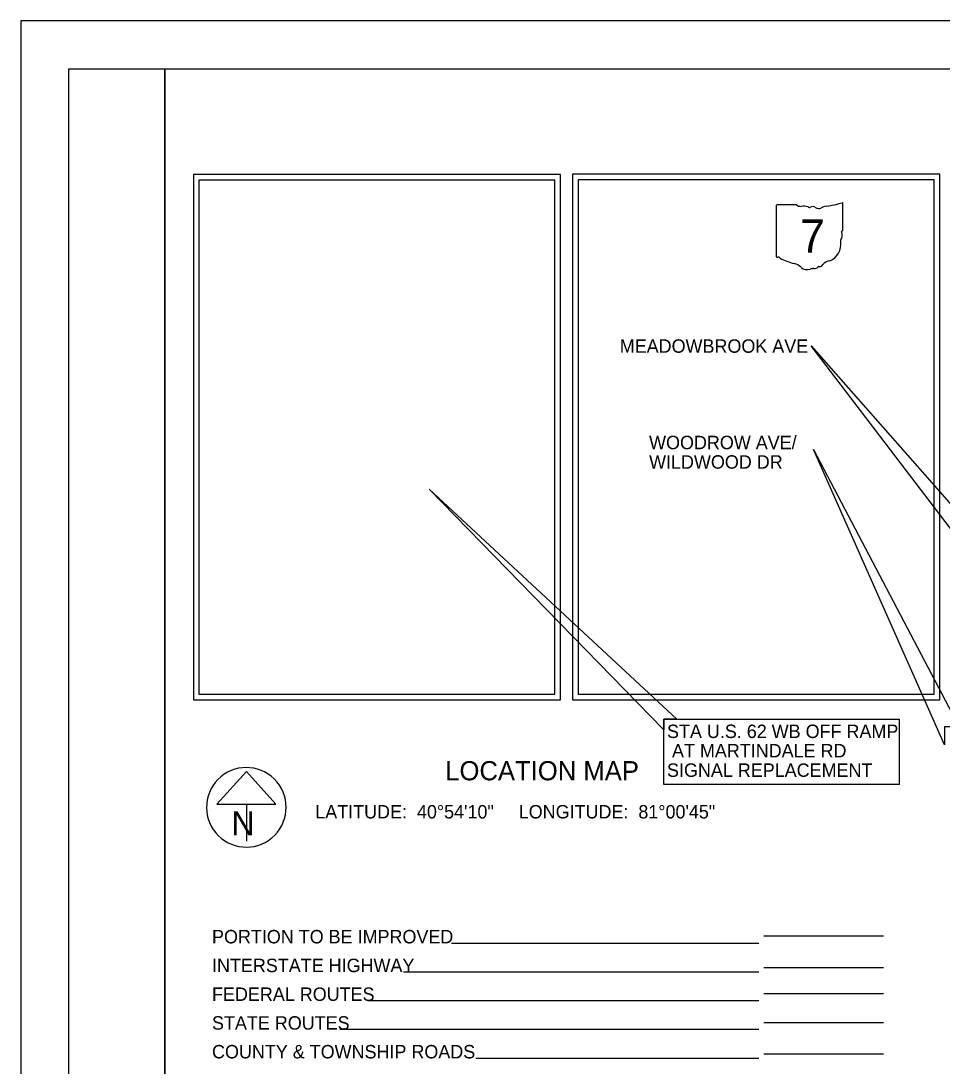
# Model space of a CAD drawing. Extents: x 0 to 29006, y 0 to 889393.
# Drawn here: x 0 to 9.61, y 11.1 to 22 of the extents above; entities that cross this region are included whole.
import ezdxf

# ---------------------------------------------------------------- set-up
doc = ezdxf.new("R2010")
doc.units = 0
for name, color, linetype in [('Default', 7, 'Continuous'), ('GM_X_State_Shield', 7, 'Continuous'), ('SH_Border', 7, 'Continuous'), ('SH_Cut_Line', 7, 'Continuous'), ('SH_Data', 7, 'Continuous'), ('SH_Text', 7, 'Continuous')]:
    doc.layers.add(name, color=color, linetype=linetype)

msp = doc.modelspace()

# ---------------------------------------------------------------- linework, layer by layer
at = {"layer": 'Default'}
for p, q in [((5.63, 20.399), (1.799, 20.399)), ((1.799, 20.399), (1.799, 14.916)), ((5.63, 14.916), (5.63, 20.399)), ((9.587, 20.401), (5.754, 20.401)), ((5.754, 20.401), (5.754, 14.916)), ((9.587, 14.916), (9.587, 20.401)), ((5.571, 20.34), (1.858, 20.34)), ((1.858, 20.34), (1.858, 14.975)), ((5.571, 14.975), (5.571, 20.34)), ((9.528, 20.342), (5.813, 20.342)), ((5.813, 20.342), (5.813, 14.975)), ((9.528, 14.975), (9.528, 20.342)), ((1.858, 14.975), (5.571, 14.975)), ((5.813, 14.975), (9.528, 14.975)), ((1.799, 14.916), (5.63, 14.916)), ((5.754, 14.916), (9.587, 14.916))]:
    msp.add_line(p, q, dxfattribs=at)
for points in [[(10.002, 16.307), (8.244, 18.612), (10.126, 16.474), (10.002, 16.474)], [(9.635, 14.448), (8.269, 17.529), (9.789, 14.637), (9.635, 14.637)], [(6.707, 14.603), (4.261, 17.114), (6.844, 14.715), (6.707, 14.715)], [(6.707, 14.715), (9.164, 14.715), (9.164, 14.036), (6.707, 14.036)]]:
    msp.add_lwpolyline(points, close=True, dxfattribs=at)
at = {"layer": 'GM_X_State_Shield'}
for p, q in [((7.88, 20.073), (7.88, 19.544)), ((8.091, 20.082), (7.887, 20.082)), ((8.576, 19.819), (8.576, 20.095)), ((8.576, 19.819), (8.576, 19.819))]:
    msp.add_line(p, q, dxfattribs=at)
for centre, radius, start, end in [((7.888, 20.074), 0.00806, 98.1301, 188.1301), ((8.139, 20.143), 0.0782, 231.6195, 271.1119), ((8.165, 19.785), 0.281, 80.4867, 94.9883), ((8.229, 20.077), 0.0226, 219.7921, 297.1024), ((8.262, 20.016), 0.0469, 54.4667, 119.1411), ((8.422, 19.92), 0.149, 97.3462, 120.7689), ((8.328, 20.802), 0.738, 275.8445, 288.9065), ((8.568, 20.096), 0.00775, 351.8621, 97.738), ((8.323, 20.099), 0.0564, 233.8562, 294.8282), ((8.604, 19.703), 0.0524, 136.8065, 186.9296), ((8.574, 19.798), 0.012, 107.944, 210.337), ((8.498, 19.763), 0.072, 340.033, 23.6496), ((8.568, 19.818), 0.00829, 289.6038, 7.7341), ((8.37, 19.668), 0.185, 292.3089, 8.9858), ((7.888, 19.543), 0.00814, 171.9584, 258.3066), ((7.889, 19.597), 0.0621, 267.339, 280.6039), ((7.902, 19.514), 0.0224, 29.7484, 93.2717), ((8.185, 19.989), 0.533, 240.4129, 257.1985), ((8.026, 19.307), 0.167, 47.1842, 75.836), ((8.206, 19.511), 0.106, 230.7004, 286.2918), ((8.267, 19.329), 0.087, 85.6951, 111.2099), ((8.275, 19.472), 0.0564, 268.777, 315.5493), ((8.326, 19.421), 0.0159, 65.7517, 132.6484), ((8.319, 19.493), 0.0597, 282.8732, 323.2771), ((8.447, 19.396), 0.101, 94.4031, 142.5768)]:
    msp.add_arc(centre, radius, start, end, dxfattribs=at)
at = {"layer": 'SH_Border'}
for points in [[(0.5, 21.5), (1.5, 21.5), (1.5, 0.5), (0.5, 0.5)], [(1.5, 21.5), (33.5, 21.5), (33.5, 0.5), (1.5, 0.5)]]:
    msp.add_lwpolyline(points, close=True, dxfattribs=at)
at = {"layer": 'SH_Cut_Line'}
msp.add_lwpolyline([(0, 0), (34, 0), (34, 22), (0, 22)], close=True, dxfattribs=at)
at = {"layer": 'SH_Data'}
for p, q in [((2.352, 14.17), (2.044, 13.829)), ((2.1, 14.1), (2.1, 14.1)), ((2.659, 13.829), (2.352, 14.17)), ((2.044, 13.829), (2.659, 13.829)), ((2.352, 13.829), (2.352, 13.442)), ((2.352, 13.796), (2.352, 13.796)), ((2.352, 13.796), (2.352, 13.796)), ((7.75, 12.455), (9, 12.455)), ((7.7, 12.377), (4.494, 12.377)), ((9, 12.121), (7.75, 12.121)), ((7.7, 12.077), (3.99, 12.077)), ((7.7, 11.777), (3.619, 11.777)), ((9, 11.849), (7.75, 11.849)), ((7.7, 11.477), (3.329, 11.477)), ((9, 11.549), (7.75, 11.549)), ((7.7, 11.177), (4.745, 11.177)), ((9, 11.222), (7.75, 11.222))]:
    msp.add_line(p, q, dxfattribs=at)
msp.add_arc((2.352, 13.796), 0.415, 129.7798, 129.7633, dxfattribs=at)

# ---------------------------------------------------------------- texts
at = {"layer": 'GM_X_State_Shield'}
msp.add_text('7', height=0.348, dxfattribs=at).set_placement((8.128, 19.582))
at = {"layer": 'SH_Data'}
msp.add_text('N', height=0.25, dxfattribs=at).set_placement((2.197, 13.505))
at = {"layer": 'SH_Text'}
for s, height, p in [('MEADOWBROOK AVE', 0.14, (6.248, 18.538)), ('WOODROW AVE/', 0.14, (6.554, 17.532)), ('WILDWOOD DR', 0.14, (6.554, 17.329)), ('STA U.S. 62 WB OFF RAMP', 0.14, (6.741, 14.519)), (' AT MARTINDALE RD', 0.14, (6.741, 14.317)), ('LOCATION MAP', 0.2, (4.427, 14.078)), ('SIGNAL REPLACEMENT', 0.14, (6.741, 14.114)), ('LATITUDE:  40°54\'10"     LONGITUDE:  81°00\'45"', 0.14, (3.071, 13.68)), ('PORTION TO BE IMPROVED', 0.14, (1.994, 12.377)), ('INTERSTATE HIGHWAY', 0.14, (1.994, 12.077)), ('FEDERAL ROUTES', 0.14, (1.994, 11.777)), ('STATE ROUTES', 0.14, (1.994, 11.477)), ('COUNTY & TOWNSHIP ROADS', 0.14, (1.994, 11.177))]:
    msp.add_text(s, height=height, dxfattribs=at).set_placement(p)

doc.saveas('drawing.dxf')
